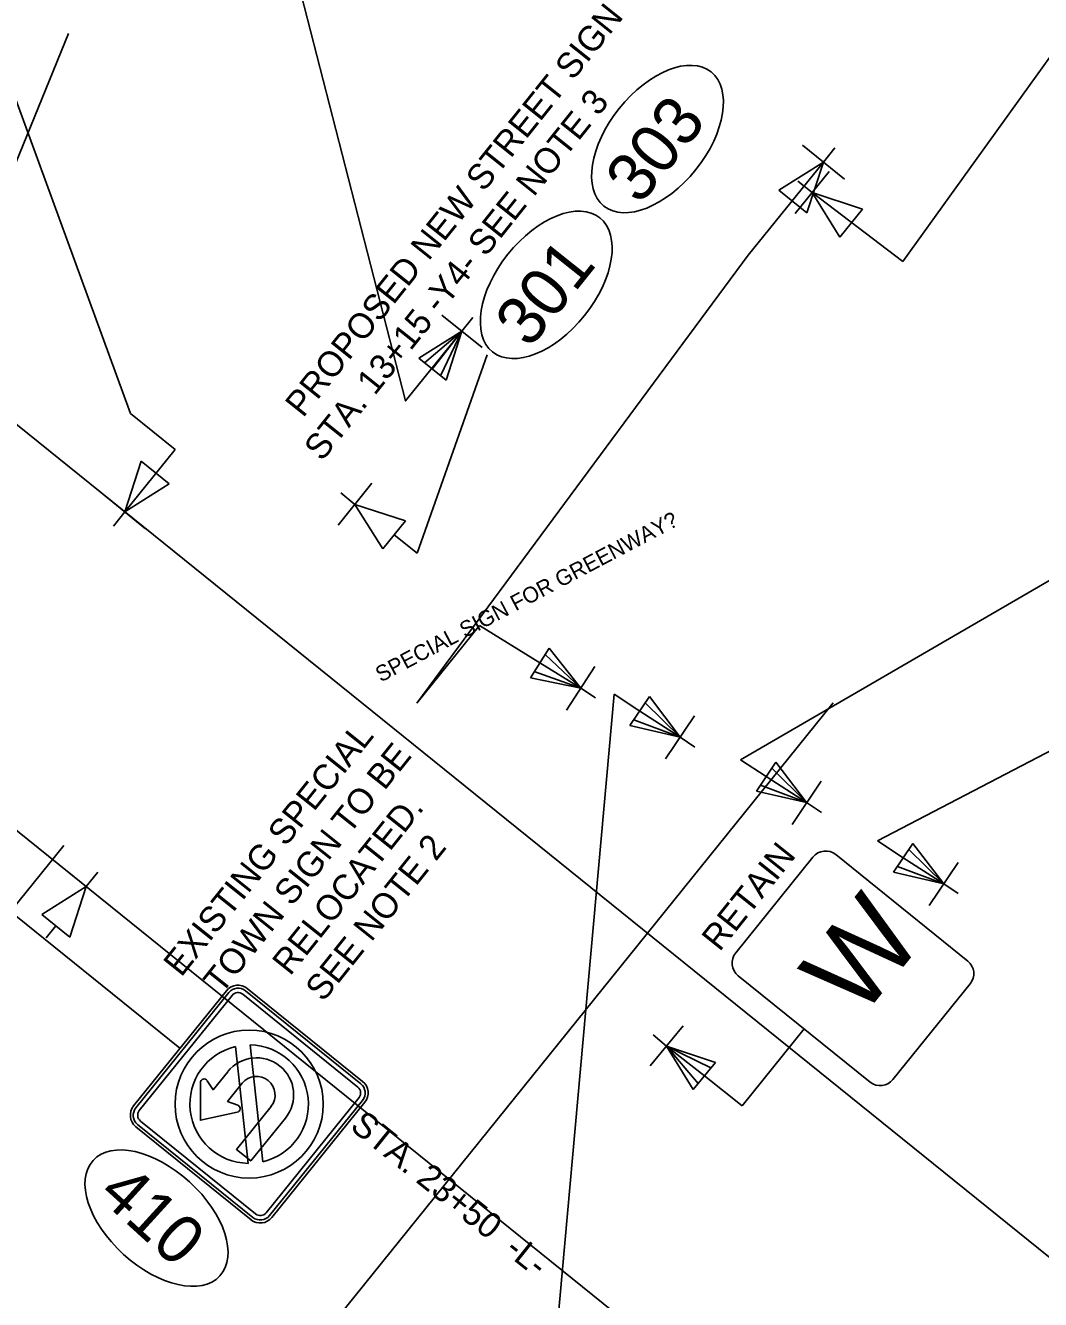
# Model space of a CAD drawing. Extents: x 1487362 to 2061618, y 497428 to 671257.
# Drawn here: x 1488800.2 to 1488928.7, y 499111.2 to 499272.6 of the extents above; entities that cross this region are included whole.
import ezdxf

# ---------------------------------------------------------------- set-up
doc = ezdxf.new("R2010")
doc.units = 0
for name, color, linetype in [('Exist Sign E', 7, 'Continuous'), ('Exist Support 1', 7, 'Continuous'), ('Prop Sign E', 7, 'Continuous'), ('Prop Sign E Object Marker CELL', 7, 'Continuous'), ('Prop Support One', 7, 'Continuous'), ('Scratch_Level_1', 7, 'Continuous'), ('Scratch_Level_5', 7, 'Continuous'), ('Text', 7, 'Continuous')]:
    doc.layers.add(name, color=color, linetype=linetype)

msp = doc.modelspace()

# ---------------------------------------------------------------- linework, layer by layer
at = {"layer": 'Exist Sign E'}
for points in [[(1488902.75, 499167.57), (1488919.45, 499154.09)], [(1488890.08, 499155.13), (1488899.86, 499167.26)], [(1488907.09, 499138.77), (1488890.39, 499152.24)], [(1488919.76, 499151.2), (1488909.98, 499139.08)]]:
    msp.add_lwpolyline(points, dxfattribs=at)
for centre, start, end in [((1488901.46, 499165.97), 51.1156, 141.1156), ((1488891.68, 499153.84), 141.1156, 231.1156), ((1488918.16, 499152.49), 321.1156, 51.1156), ((1488908.38, 499140.37), 231.1156, 321.1156)]:
    msp.add_arc(centre, 2.06, start, end, dxfattribs=at)
at = {"layer": 'Exist Support 1'}
for p, q in [((1488857.99, 499231.78), (1488852.86, 499235.91)), ((1488855.4, 499233.86), (1488856.81, 499235.6)), ((1488855.4, 499233.86), (1488849.95, 499230.44)), ((1488850.69, 499229.84), (1488855.4, 499233.86)), ((1488851.66, 499229.06), (1488855.4, 499233.86)), ((1488852.69, 499228.23), (1488855.4, 499233.86)), ((1488855.4, 499233.86), (1488853.4, 499227.66)), ((1488853.4, 499227.66), (1488849.95, 499230.44)), ((1488890.68, 499179.59), (1488966.62, 499223.68)), ((1488908.03, 499169.31), (1488999.69, 499217.15)), ((1488849.72, 499186.76), (1488857.65, 499196.6)), ((1488865.29, 499191.87), (1488857.65, 499196.6)), ((1488864.08, 499189.98), (1488866.48, 499193.7)), ((1488870.46, 499188.65), (1488866.48, 499193.7)), ((1488865.29, 499191.85), (1488870.46, 499188.65)), ((1488865.96, 499192.9), (1488870.46, 499188.65)), ((1488870.46, 499188.65), (1488864.08, 499189.98)), ((1488864.57, 499190.75), (1488870.46, 499188.65)), ((1488868.67, 499185.86), (1488872.23, 499191.39)), ((1488870.46, 499188.65), (1488872.34, 499187.43)), ((1488874.67, 499187.88), (1488861.31, 499038.78)), ((1488877.93, 499185.76), (1488874.67, 499187.88)), ((1488876.69, 499183.91), (1488879.15, 499187.58)), ((1488878.62, 499186.79), (1488883.04, 499182.45)), ((1488883.04, 499182.45), (1488879.15, 499187.58)), ((1488877.93, 499185.76), (1488883.04, 499182.45)), ((1488881.2, 499179.7), (1488884.86, 499185.16)), ((1488883.04, 499182.45), (1488876.69, 499183.91)), ((1488877.19, 499184.66), (1488883.04, 499182.45)), ((1488883.04, 499182.45), (1488884.9, 499181.2)), ((1488893.95, 499177.46), (1488890.68, 499179.59)), ((1488892.71, 499175.61), (1488895.17, 499179.28)), ((1488899.06, 499174.16), (1488895.17, 499179.28)), ((1488893.95, 499177.46), (1488899.06, 499174.16)), ((1488894.64, 499178.5), (1488899.06, 499174.16)), ((1488899.06, 499174.16), (1488892.71, 499175.61)), ((1488893.21, 499176.37), (1488899.06, 499174.16)), ((1488897.22, 499171.4), (1488900.88, 499176.87)), ((1488899.06, 499174.16), (1488900.92, 499172.91)), ((1488911.29, 499167.18), (1488908.03, 499169.31)), ((1488910.05, 499165.33), (1488912.51, 499169)), ((1488916.41, 499163.87), (1488912.51, 499169)), ((1488911.99, 499168.21), (1488916.41, 499163.87)), ((1488910.56, 499166.08), (1488916.41, 499163.87)), ((1488911.29, 499167.18), (1488916.41, 499163.87)), ((1488914.56, 499161.12), (1488918.22, 499166.59)), ((1488916.41, 499163.87), (1488910.05, 499165.33)), ((1488916.41, 499163.87), (1488918.26, 499162.63)), ((1488883.44, 499145.89), (1488879.26, 499140.8)), ((1488881.33, 499143.32), (1488879.61, 499144.74)), ((1488890.88, 499135.76), (1488898.74, 499145.5)), ((1488881.33, 499143.32), (1488884.71, 499137.84)), ((1488881.33, 499143.32), (1488887.52, 499141.26)), ((1488886.11, 499139.54), (1488881.33, 499143.32)), ((1488886.94, 499140.56), (1488881.33, 499143.32)), ((1488885.32, 499138.58), (1488881.33, 499143.32)), ((1488887.52, 499141.26), (1488884.71, 499137.84)), ((1488886.11, 499139.54), (1488890.88, 499135.76))]:
    msp.add_line(p, q, dxfattribs=at)
msp.add_lwpolyline([(1488855.4, 499233.86), (1488848.29, 499225.04), (1488834.65, 499278.18)], dxfattribs=at)
at = {"layer": 'Prop Sign E'}
for centre in [(1488880.18, 499258.2), (1488866.09, 499239.73)]:
    msp.add_ellipse(centre, major_axis=(6.79, 8.49), ratio=0.571429, dxfattribs=at)
at = {"layer": 'Prop Sign E Object Marker CELL'}
for p, q in [((1488813.84, 499135.74), (1488825.61, 499150.33)), ((1488814.13, 499135.5), (1488825.9, 499150.1)), ((1488814.57, 499135.15), (1488826.34, 499149.74)), ((1488827.66, 499149.89), (1488842.25, 499138.12)), ((1488828.01, 499150.32), (1488842.6, 499138.55)), ((1488828.24, 499150.62), (1488842.84, 499138.85)), ((1488826.76, 499143.27), (1488828.34, 499128.47)), ((1488830.2, 499128.67), (1488828.62, 499143.47)), ((1488842.39, 499136.8), (1488830.62, 499122.2)), ((1488842.83, 499136.44), (1488831.06, 499121.85)), ((1488843.12, 499136.21), (1488831.35, 499121.61)), ((1488829.3, 499122.06), (1488814.71, 499133.83)), ((1488828.72, 499121.33), (1488814.12, 499133.1)), ((1488828.95, 499121.62), (1488814.36, 499133.39))]:
    msp.add_line(p, q, dxfattribs=at)
for points in [[(1488825.77, 499140.08), (1488823.92, 499137.79), (1488823.18, 499138.94)], [(1488822.31, 499138.69), (1488822.31, 499133.92), (1488826.97, 499134.94)], [(1488827.03, 499135.83), (1488825.75, 499136.32), (1488827.6, 499138.61)], [(1488831.25, 499135.67), (1488826.87, 499130.24), (1488828.69, 499128.77), (1488833.07, 499134.2)]]:
    msp.add_lwpolyline(points, dxfattribs=at)
msp.add_circle((1488828.48, 499135.97), 9.37, dxfattribs=at)
for centre, radius, start, end in [((1488827.07, 499149.16), 1.87, 51.1156, 141.1156), ((1488827.07, 499149.16), 1.5, 51.1156, 141.1156), ((1488827.07, 499149.16), 0.937, 51.1156, 141.1156), ((1488828.48, 499135.97), 7.5, 103.2964, 268.9349), ((1488828.48, 499135.97), 7.5, 283.2964, 88.9349), ((1488829.42, 499137.14), 4.69, 321.1156, 141.1156), ((1488822.78, 499138.69), 0.469, 32.8035, 179.9188), ((1488829.42, 499137.14), 2.34, 321.1156, 141.1156), ((1488841.66, 499137.39), 1.5, 321.1156, 51.1156), ((1488841.66, 499137.39), 1.88, 321.1156, 51.1156), ((1488841.66, 499137.39), 0.937, 321.1156, 51.1156), ((1488815.3, 499134.56), 1.87, 141.1156, 231.1156), ((1488815.3, 499134.56), 1.5, 141.1156, 231.1156), ((1488815.3, 499134.56), 0.937, 141.1156, 231.1156), ((1488826.87, 499135.39), 0.469, 282.3125, 69.4278), ((1488829.89, 499122.79), 0.937, 231.1156, 321.1156), ((1488829.89, 499122.79), 1.88, 231.1156, 321.1156), ((1488829.89, 499122.79), 1.5, 231.1156, 321.1156)]:
    msp.add_arc(centre, radius, start, end, dxfattribs=at)
msp.add_ellipse((1488816.75, 499121.53), major_axis=(-8.03, 7.32), ratio=0.571429, dxfattribs=at)
at = {"layer": 'Prop Support One'}
for p, q in [((1488911.23, 499242.69), (1488975.77, 499332.48)), ((1488813.47, 499223.44), (1488777.88, 499320.7)), ((1488903.85, 499253.13), (1488898.55, 499257.41)), ((1488901.18, 499255.29), (1488902.63, 499257.09)), ((1488895.54, 499251.74), (1488901.18, 499255.29)), ((1488901.18, 499255.29), (1488899.1, 499248.87)), ((1488901.9, 499254.08), (1488897.62, 499248.78)), ((1488899.74, 499251.41), (1488897.94, 499252.86)), ((1488899.1, 499248.87), (1488895.54, 499251.74)), ((1488903.28, 499245.77), (1488899.74, 499251.41)), ((1488899.74, 499251.41), (1488906.15, 499249.33)), ((1488899.74, 499251.41), (1488911.23, 499242.69)), ((1488906.15, 499249.33), (1488903.28, 499245.77)), ((1488858.61, 499230.86), (1488849.75, 499205.73)), ((1488819.12, 499218.89), (1488813.47, 499223.44)), ((1488812.74, 499210.97), (1488819.12, 499218.89)), ((1488812.74, 499210.97), (1488814.81, 499217.39)), ((1488814.81, 499217.39), (1488818.37, 499214.52)), ((1488818.37, 499214.52), (1488812.74, 499210.97)), ((1488844.02, 499214.6), (1488839.75, 499209.3)), ((1488810.07, 499213.13), (1488815.36, 499208.85)), ((1488841.87, 499211.93), (1488840.07, 499213.38)), ((1488812.74, 499210.97), (1488811.29, 499209.17)), ((1488845.41, 499206.29), (1488841.87, 499211.93)), ((1488841.87, 499211.93), (1488848.28, 499209.85)), ((1488848.28, 499209.85), (1488845.41, 499206.29)), ((1488846.85, 499208.07), (1488849.75, 499205.73)), ((1488782.29, 499173.22), (1488819.72, 499143.04))]:
    msp.add_line(p, q, dxfattribs=at)
msp.add_lwpolyline([(1488901.18, 499255.29), (1488891.67, 499243.5), (1488849.72, 499186.76)], dxfattribs=at)
at = {"layer": 'Scratch_Level_1'}
for p, q in [((1488657.05, 499336.52), (1488968.42, 499085.42)), ((1488943.31, 499054.29), (1488631.94, 499305.39)), ((1488651.33, 498875.42), (1488902.43, 499186.79)), ((1488775.15, 499131.71), (1488805, 499168.72))]:
    msp.add_line(p, q, dxfattribs=at)
at = {"layer": 'Scratch_Level_5'}
for p, q in [((1488792.88, 499240.37), (1488805.62, 499271.56)), ((1488810.52, 499161.37), (1488805.23, 499165.65)), ((1488807.85, 499163.53), (1488809.3, 499165.33)), ((1488802.22, 499159.98), (1488807.85, 499163.53)), ((1488807.85, 499163.53), (1488805.77, 499157.11)), ((1488805.77, 499157.11), (1488802.22, 499159.98)), ((1488802.77, 499157.03), (1488804, 499158.55))]:
    msp.add_line(p, q, dxfattribs=at)

# ---------------------------------------------------------------- texts
at = {"layer": 'Exist Sign E'}
msp.add_text('W', height=10.38, rotation=51.1156, dxfattribs=at).set_placement((1488905.85, 499146.58))
at = {"layer": 'Prop Sign E'}
for s, p in [('303', (1488877.95, 499249.73)), ('301', (1488863.98, 499231.55))]:
    msp.add_text(s, height=6.136, rotation=51.3436, dxfattribs=at).set_placement(p)
at = {"layer": 'Prop Sign E Object Marker CELL'}
for s, height, rotation, p in [('STA. 23+50  -L-', 3.2, 321.2915, (1488841.1, 499132.89)), ('410', 6.136, 317.6747, (1488809.16, 499124.29))]:
    msp.add_text(s, height=height, rotation=rotation, dxfattribs=at).set_placement(p)
at = {"layer": 'Scratch_Level_1'}
msp.add_text('SPECIAL SIGN FOR GREENWAY?', height=2, rotation=27.8351, dxfattribs=at).set_placement((1488845.14, 499189.35))
at = {"layer": 'Text'}
for s, p in [('PROPOSED NEW STREET SIGN', (1488835.3, 499222.8)), ('STA. 13+15 -Y4- SEE NOTE 3', (1488837.69, 499217.26)), ('EXISTING SPECIAL ', (1488819.88, 499151.95)), ('TOWN SIGN TO BE ', (1488824.97, 499149.78)), ('RELOCATED.', (1488833.66, 499152.11)), ('SEE NOTE 2', (1488837.85, 499148.8)), ('RETAIN', (1488888.03, 499155.18))]:
    msp.add_text(s, height=3.2, rotation=51.3435, dxfattribs=at).set_placement(p)

doc.saveas('drawing.dxf')
